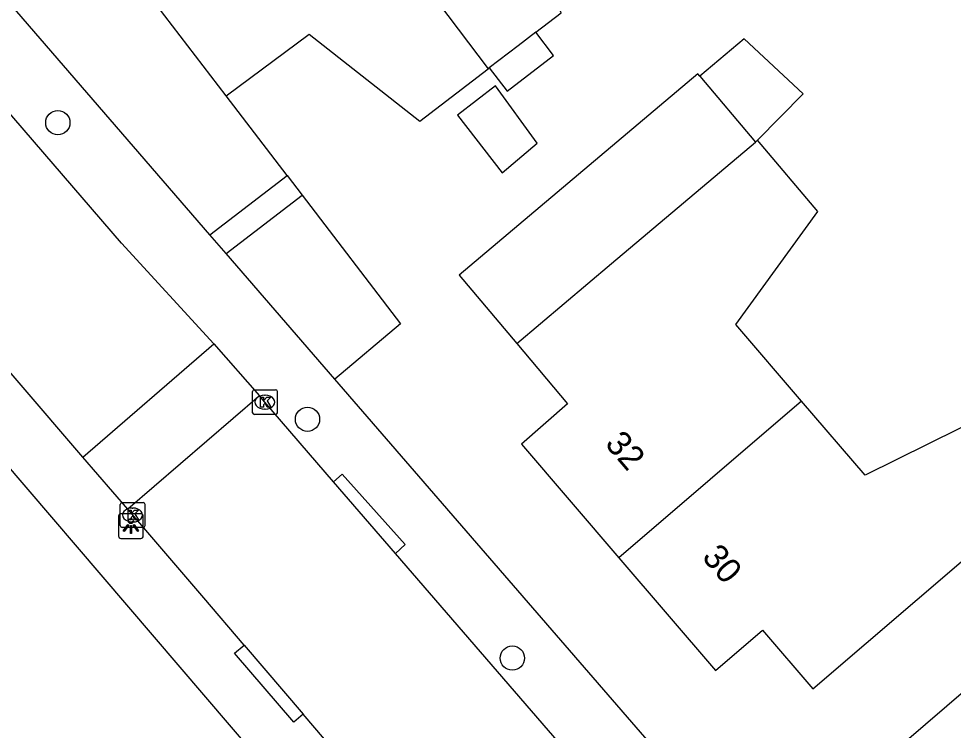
# Model space of a CAD drawing. Extents: x 159353 to 160616, y 385893 to 387321.
# Drawn here: x 160058.68 to 160096.35, y 386562.21 to 386590.9 of the extents above; entities that cross this region are included whole.
import ezdxf

# ---------------------------------------------------------------- set-up
doc = ezdxf.new("R2010")
doc.units = 0
for name, color, linetype in [('IMGEO_Boom', 7, 'Continuous'), ('IMGEO_Groenvoorziening', 7, 'Continuous'), ('IMGEO_Kolk', 7, 'Continuous'), ('IMGEO_Lichtpunt', 7, 'Continuous'), ('IMGEO_Muur', 7, 'Continuous'), ('IMGEO_Pand', 7, 'Continuous'), ('IMGEO_Pand_nummerreeks', 7, 'Continuous'), ('IMGEO_Rijbaan_lokaal_open', 7, 'Continuous'), ('IMGEO_Voetpad_open', 7, 'Continuous')]:
    doc.layers.add(name, color=color, linetype=linetype)

msp = doc.modelspace()

# ---------------------------------------------------------------- linework, layer by layer
at = {"layer": 'IMGEO_Boom'}
for centre in [(160060.261, 386586.707), (160070.324, 386574.75), (160078.582, 386565.123)]:
    msp.add_circle(centre, 0.489, dxfattribs=at)
at = {"layer": 'IMGEO_Groenvoorziening'}
for points in [[(160069.506, 386584.574), (160067.05, 386587.783)], [(160070.113, 386583.782), (160074.078, 386578.601), (160071.431, 386576.368)]]:
    msp.add_lwpolyline(points, dxfattribs=at)
at = {"layer": 'IMGEO_Kolk'}
for p, q in [((160068.107, 386575.015), (160068.107, 386575.867)), ((160068.182, 386575.941), (160069.034, 386575.941)), ((160068.595, 386575.721), (160068.62, 386575.721)), ((160069.108, 386575.867), (160069.108, 386575.015)), ((160069.034, 386574.941), (160068.182, 386574.941)), ((160068.618, 386575.161), (160068.593, 386575.161)), ((160062.773, 386570.466), (160062.773, 386571.318)), ((160062.848, 386571.392), (160063.7, 386571.392)), ((160063.261, 386571.172), (160063.286, 386571.172)), ((160063.774, 386571.318), (160063.774, 386570.466)), ((160063.7, 386570.392), (160062.848, 386570.392)), ((160063.284, 386570.612), (160063.259, 386570.612))]:
    msp.add_line(p, q, dxfattribs=at)
for points in [[(160068.107, 386575.015), (160068.107, 386575.867)], [(160068.182, 386575.941), (160069.034, 386575.941)], [(160068.428, 386575.641), (160068.551, 386575.641), (160068.551, 386575.49), (160068.681, 386575.641), (160068.845, 386575.641), (160068.699, 386575.49), (160068.852, 386575.241), (160068.7, 386575.241), (160068.615, 386575.405), (160068.551, 386575.338), (160068.551, 386575.241), (160068.428, 386575.241), (160068.428, 386575.641)], [(160069.108, 386575.867), (160069.108, 386575.015)], [(160069.034, 386574.941), (160068.182, 386574.941)], [(160062.773, 386570.466), (160062.773, 386571.318)], [(160062.848, 386571.392), (160063.7, 386571.392)], [(160063.774, 386571.318), (160063.774, 386570.466)], [(160063.094, 386571.092), (160063.217, 386571.092), (160063.217, 386570.941), (160063.347, 386571.092), (160063.511, 386571.092), (160063.365, 386570.941), (160063.518, 386570.692), (160063.366, 386570.692), (160063.281, 386570.856), (160063.217, 386570.789), (160063.217, 386570.692), (160063.094, 386570.692), (160063.094, 386571.092)], [(160063.7, 386570.392), (160062.848, 386570.392)]]:
    msp.add_lwpolyline(points, dxfattribs=at)
for centre, start, end in [((160068.184, 386575.865), 91.552, 178.448), ((160068.184, 386575.865), 91.552, 178.448), ((160069.032, 386575.865), 1.552, 88.448), ((160069.032, 386575.865), 1.552, 88.448), ((160068.184, 386575.017), 181.552, 268.448), ((160068.184, 386575.017), 181.552, 268.448), ((160069.032, 386575.017), 271.552, 358.448), ((160069.032, 386575.017), 271.552, 358.448), ((160062.85, 386571.316), 91.552, 178.448), ((160062.85, 386571.316), 91.552, 178.448), ((160063.698, 386571.316), 1.552, 88.448), ((160063.698, 386571.316), 1.552, 88.448), ((160062.85, 386570.468), 181.552, 268.448), ((160062.85, 386570.468), 181.552, 268.448), ((160063.698, 386570.468), 271.552, 358.448), ((160063.698, 386570.468), 271.552, 358.448)]:
    msp.add_arc(centre, 0.0765, start, end, dxfattribs=at)
for centre, major_axis, ratio, start_param, end_param in [((160068.594, 386575.441), (-0.387, 0.002), 0.722429, 4.712389, 7.853982), ((160068.619, 386575.441), (-0.39, 0.002), 0.717154, 1.570796, 4.712389), ((160063.26, 386570.892), (-0.387, 0.002), 0.722429, 4.712389, 7.853982), ((160063.285, 386570.892), (-0.39, 0.002), 0.717154, 1.570796, 4.712389)]:
    msp.add_ellipse(centre, major_axis=major_axis, ratio=ratio, start_param=start_param, end_param=end_param, dxfattribs=at)
at = {"layer": 'IMGEO_Lichtpunt'}
for p, q in [((160062.708, 386570.849), (160062.708, 386570.042)), ((160062.708, 386570.849), (160062.708, 386570.042)), ((160063.61, 386570.944), (160062.802, 386570.944)), ((160063.61, 386570.944), (160062.802, 386570.944)), ((160063.704, 386570.042), (160063.704, 386570.849)), ((160063.704, 386570.042), (160063.704, 386570.849)), ((160062.802, 386569.948), (160063.61, 386569.948)), ((160062.802, 386569.948), (160063.61, 386569.948))]:
    msp.add_line(p, q, dxfattribs=at)
for points in [[(160063.082, 386570.513), (160063.121, 386570.485), (160062.933, 386570.223), (160062.895, 386570.25), (160063.082, 386570.513)], [(160063.184, 386570.465), (160063.231, 386570.465), (160063.231, 386570.143), (160063.184, 386570.143), (160063.184, 386570.465)], [(160063.294, 386570.485), (160063.332, 386570.512), (160063.519, 386570.25), (160063.48, 386570.222), (160063.294, 386570.485)]]:
    msp.add_lwpolyline(points, dxfattribs=at)
msp.add_circle((160063.207, 386570.647), 0.0994, dxfattribs=at)
for centre, start, end in [((160062.802, 386570.849), 90, 180), ((160062.802, 386570.849), 90, 180), ((160063.61, 386570.849), 0, 90), ((160063.61, 386570.849), 0, 90), ((160062.802, 386570.042), 180, 270), ((160062.802, 386570.042), 180, 270), ((160063.61, 386570.042), 270, 0), ((160063.61, 386570.042), 270, 360)]:
    msp.add_arc(centre, 0.0946, start, end, dxfattribs=at)
at = {"layer": 'IMGEO_Muur'}
msp.add_lwpolyline([(160093.321, 386560.82), (160105.45, 386571.234)], dxfattribs=at)
at = {"layer": 'IMGEO_Pand'}
for points in [[(160069.934, 386599.037), (160077.608, 386588.881)], [(160079.522, 386590.351), (160080.543, 386591.136), (160078.303, 386596.351), (160081.392, 386598.724)], [(160067.05, 386587.783), (160061.18, 386595.452)], [(160079.522, 386590.351), (160078.815, 386589.808), (160077.653, 386588.916)], [(160077.653, 386588.916), (160078.374, 386587.978), (160080.242, 386589.414), (160079.522, 386590.351)], [(160067.05, 386587.783), (160070.389, 386590.271), (160074.849, 386586.762), (160077.608, 386588.881)], [(160088.464, 386585.997), (160090.304, 386587.871), (160087.925, 386590.08), (160086.141, 386588.581)], [(160077.608, 386588.881), (160077.653, 386588.916)], [(160086.141, 386588.581), (160086.062, 386588.675), (160076.439, 386580.553), (160078.758, 386577.805)], [(160086.141, 386588.581), (160088.375, 386585.922)], [(160076.364, 386587.003), (160078.17, 386584.681), (160079.586, 386585.876), (160077.895, 386588.194), (160076.364, 386587.003)], [(160078.758, 386577.805), (160082.579, 386581.03), (160088.375, 386585.922)], [(160090.234, 386575.485), (160087.59, 386578.568), (160090.89, 386583.124), (160088.464, 386585.997)], [(160088.375, 386585.922), (160088.464, 386585.997)], [(160078.758, 386577.805), (160080.809, 386575.375), (160078.949, 386573.751), (160082.875, 386569.169)], [(160090.234, 386575.485), (160082.875, 386569.169)], [(160099.356, 386571.309), (160100.338, 386572.15), (160097.886, 386575.013), (160092.798, 386572.495), (160090.234, 386575.485)], [(160082.875, 386569.169), (160086.764, 386564.629), (160088.663, 386566.256), (160090.693, 386563.887), (160097.044, 386569.328)]]:
    msp.add_lwpolyline(points, dxfattribs=at)
at = {"layer": 'IMGEO_Rijbaan_lokaal_open'}
for points in [[(160066.549, 386577.796), (160062.824, 386581.843), (160054.138, 386591.935)], [(160061.27, 386573.228), (160048.58, 386588.011)], [(160061.27, 386573.228), (160066.549, 386577.796)], [(160066.549, 386577.796), (160068.394, 386575.697)], [(160068.394, 386575.697), (160063.077, 386571.123)], [(160071.37, 386572.228), (160068.607, 386575.44), (160068.394, 386575.697)], [(160063.077, 386571.123), (160061.27, 386573.228)], [(160073.868, 386569.344), (160071.37, 386572.228)], [(160067.766, 386565.648), (160066.145, 386567.549), (160063.077, 386571.123)], [(160081.403, 386560.618), (160073.868, 386569.344)], [(160067.766, 386565.648), (160070.147, 386562.861)], [(160077.486, 386554.26), (160070.147, 386562.861)]]:
    msp.add_lwpolyline(points, dxfattribs=at)
at = {"layer": 'IMGEO_Voetpad_open'}
for points in [[(160090.811, 386558.67), (160093.321, 386560.82), (160105.45, 386571.234), (160152.311, 386611.469)], [(160066.392, 386582.19), (160056.457, 386593.67), (160056.206, 386594.041), (160056.092, 386594.363), (160056.003, 386595.124)], [(160066.392, 386582.19), (160069.506, 386584.574)], [(160069.506, 386584.574), (160070.113, 386583.782)], [(160067.046, 386581.434), (160070.113, 386583.782)], [(160067.046, 386581.434), (160066.392, 386582.19)], [(160071.431, 386576.368), (160067.046, 386581.434)], [(160052.835, 386579.175), (160068.208, 386561.23)], [(160086.602, 386558.839), (160071.431, 386576.368)], [(160071.37, 386572.228), (160071.72, 386572.541), (160074.262, 386569.697), (160073.868, 386569.344)], [(160070.147, 386562.861), (160069.767, 386562.537), (160067.386, 386565.324), (160067.766, 386565.648)]]:
    msp.add_lwpolyline(points, dxfattribs=at)

# ---------------------------------------------------------------- texts
at = {"layer": 'IMGEO_Pand_nummerreeks'}
for s, p in [('32', (160082.277, 386573.74)), ('30', (160086.188, 386569.174))]:
    msp.add_text(s, height=1, rotation=310.5881, dxfattribs=at).set_placement(p)

doc.saveas('drawing.dxf')
